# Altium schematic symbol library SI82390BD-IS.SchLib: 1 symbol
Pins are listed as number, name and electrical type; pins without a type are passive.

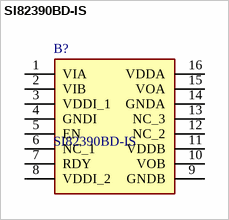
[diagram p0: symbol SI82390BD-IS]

## SI82390BD-IS
designator B?
Gate Drivers 5 kV 8 V UVLO dual isolated gate driver; Manufacturer_Name: Skyworks; Geometry.Height: 2.65mm
footprint SOIC127P1030X265-16N
pins: 1 VIA, 2 VIB, 3 VDDI_1, 4 GNDI, 5 EN, 6 NC_1, 7 RDY, 8 VDDI_2, 9 GNDB, 10 VOB, 11 VDDB, 12 NC_2, 13 NC_3, 14 GNDA, 15 VOA, 16 VDDA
